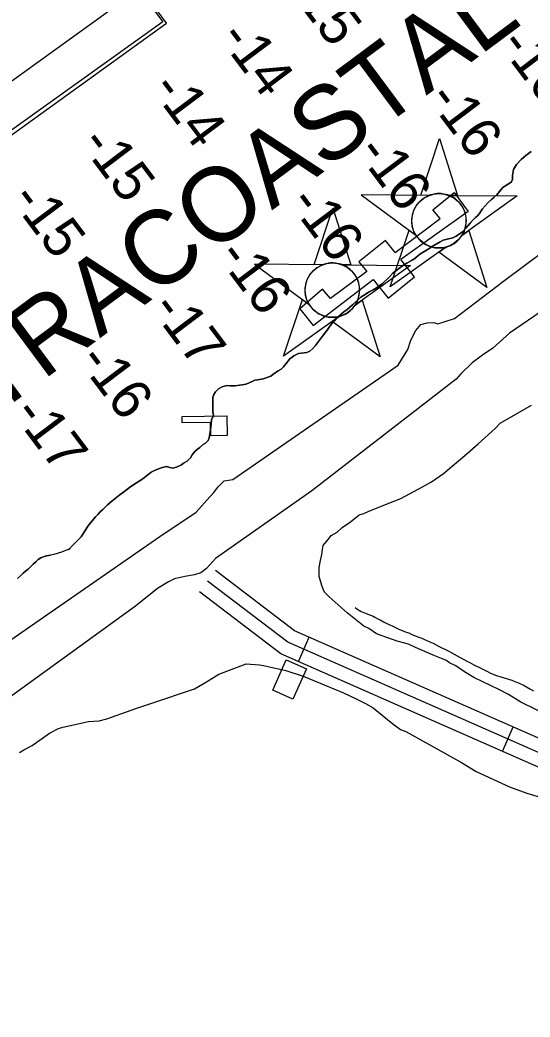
# Model space of a CAD drawing. Extents: x 3683613 to 3738215, y 469626 to 495384.
# Drawn here: x 3689919 to 3690491, y 487753 to 488872 of the extents above; entities that cross this region are included whole.
import ezdxf

# ---------------------------------------------------------------- set-up
doc = ezdxf.new("R2010")
doc.units = 0
for name, color, linetype in [('V-BLDG-OTLN', 7, 'Continuous'), ('V-CHAN-DOCK', 7, 'Continuous'), ('V-CHAN-NAID', 7, 'Continuous'), ('V-LEVE-TOET', 7, 'Continuous'), ('V-RIVR-IDEN', 7, 'Continuous'), ('V-RIVR-JETY', 7, 'Continuous'), ('V-ROAD-CNTR', 7, 'Continuous'), ('V-SITE-VEGE', 7, 'Continuous'), ('V-TOPO-SHOR', 7, 'Continuous'), ('V-TOPO-SPOT', 7, 'Continuous')]:
    doc.layers.add(name, color=color, linetype=linetype)

msp = doc.modelspace()

# ---------------------------------------------------------------- linework, layer by layer
at = {"layer": 'V-BLDG-OTLN'}
msp.add_lwpolyline([(3690217.4, 488154.1), (3690240, 488144), (3690224.8, 488109.9), (3690202.3, 488119.9)], close=True, dxfattribs=at)
at = {"layer": 'V-CHAN-DOCK'}
for points in [[(3689729.2, 488673.5), (3690051.7, 488906.3), (3690078.8, 488869.6), (3689754.7, 488637.6), (3689729.2, 488673.5)], [(3690339.7, 488610.8), (3690390.2, 488648.8), (3690382, 488658.8), (3690406, 488677.9), (3690421.6, 488656.8), (3690345.9, 488602.9)], [(3690339.7, 488610.8), (3690328.9, 488624.4), (3690298.9, 488600.5), (3690307.8, 488589.4)], [(3690314.9, 488580.4), (3690331.6, 488559.5), (3690361.5, 488583.4), (3690345.9, 488602.9)], [(3690307.8, 488589.4), (3690266.9, 488559.2), (3690258.1, 488569.5), (3690232.8, 488547.7), (3690247.8, 488528.9), (3690314.9, 488580.4)], [(3690100.5, 488426.7), (3690150.7, 488427.6), (3690151, 488405.6), (3690132.9, 488405.3), (3690132.6, 488420.1), (3690100.6, 488419.6), (3690100.5, 488426.7)]]:
    msp.add_lwpolyline(points, dxfattribs=at)
at = {"layer": 'V-CHAN-NAID'}
for points in [[(3690378, 488674.9), (3690368.4, 488675), (3690389.5, 488738.5), (3690409.7, 488674.7), (3690400.1, 488674.8), (3690398.6, 488675.3), (3690396.5, 488676), (3690394.4, 488676.4), (3690392.4, 488676.7), (3690391.2, 488676.8), (3690389.7, 488676.9), (3690388, 488676.9), (3690386.6, 488676.8), (3690384.7, 488676.6), (3690383.3, 488676.4), (3690381.5, 488676), (3690380, 488675.6), (3690379, 488675.3)], [(3690378, 488674.9), (3690301.5, 488675.5), (3690363, 488630.1), (3690361.9, 488632), (3690361.1, 488633.6), (3690360.3, 488635.6), (3690359.6, 488637.6), (3690359.2, 488638.9), (3690358.9, 488640.6), (3690358.6, 488642), (3690358.4, 488643.6), (3690358.3, 488645.4), (3690358.3, 488646.9), (3690358.4, 488649), (3690358.6, 488650.6), (3690359, 488652.8), (3690359.5, 488654.7), (3690360.1, 488656.6), (3690360.7, 488658.3), (3690361.5, 488659.9), (3690362.3, 488661.4), (3690363.3, 488663.2), (3690364.4, 488664.6), (3690365.4, 488665.9), (3690366.4, 488667.1), (3690367.7, 488668.4), (3690368.7, 488669.4), (3690370.4, 488670.8), (3690371.7, 488671.6), (3690373.3, 488672.7), (3690375.1, 488673.6), (3690376.5, 488674.3)], [(3690400.1, 488674.8), (3690476.6, 488674.2), (3690414.4, 488629.7), (3690415.3, 488631.2), (3690416.3, 488633), (3690417, 488634.6), (3690417.8, 488636.6), (3690418.3, 488638.4), (3690418.7, 488640), (3690419.1, 488642), (3690419.3, 488643.6), (3690419.4, 488645.8), (3690419.3, 488647.8), (3690419.2, 488650.1), (3690418.9, 488651.8), (3690418.4, 488654.1), (3690417.8, 488656.2), (3690417, 488658.2), (3690416.4, 488659.6), (3690415.4, 488661.5), (3690414.3, 488663.3), (3690413.1, 488665), (3690411.8, 488666.5), (3690410.5, 488667.9), (3690408.9, 488669.4), (3690407.2, 488670.8), (3690405.5, 488672), (3690403.6, 488673.1), (3690402.1, 488673.9)], [(3690258.3, 488597.1), (3690248.7, 488597.2), (3690269.8, 488660.7), (3690290, 488596.9), (3690280.4, 488597), (3690278.9, 488597.6), (3690276.8, 488598.2), (3690274.7, 488598.6), (3690272.7, 488598.9), (3690271.5, 488599), (3690270, 488599.1), (3690268.3, 488599.1), (3690266.9, 488599.1), (3690265, 488598.9), (3690263.6, 488598.6), (3690261.8, 488598.2), (3690260.3, 488597.8), (3690259.3, 488597.5)], [(3690396.4, 488616.8), (3690334.2, 488572.3), (3690355.3, 488635.8), (3690363, 488630.1), (3690363.7, 488629.1), (3690365, 488627.2), (3690366.3, 488625.8), (3690367.7, 488624.3), (3690369.1, 488623.1), (3690370.6, 488621.9), (3690372, 488620.9), (3690373.6, 488619.9), (3690375.4, 488619), (3690377.2, 488618.2), (3690378.6, 488617.6), (3690380.2, 488617.1), (3690382.5, 488616.5), (3690384, 488616.2), (3690386, 488616), (3690387.5, 488615.9), (3690389.4, 488615.9), (3690391.1, 488615.9), (3690392.8, 488616.1), (3690394.7, 488616.4)], [(3690414.4, 488629.7), (3690422.2, 488635.3), (3690442.4, 488571.5), (3690388.6, 488611.2), (3690396.4, 488616.8), (3690398.1, 488617.3), (3690399.7, 488617.8), (3690401.8, 488618.7), (3690403.6, 488619.6), (3690405.4, 488620.7), (3690407.2, 488622), (3690408.7, 488623.2), (3690410, 488624.4), (3690411.4, 488625.8), (3690412.6, 488627.2), (3690413.7, 488628.7)], [(3690258.3, 488597.1), (3690181.8, 488597.7), (3690243.3, 488552.3), (3690242.2, 488554.2), (3690241.4, 488555.8), (3690240.6, 488557.8), (3690239.9, 488559.8), (3690239.5, 488561.2), (3690239.2, 488562.8), (3690238.9, 488564.2), (3690238.7, 488565.8), (3690238.6, 488567.6), (3690238.6, 488569.1), (3690238.7, 488571.2), (3690238.9, 488572.8), (3690239.3, 488575), (3690239.8, 488577), (3690240.4, 488578.8), (3690241, 488580.5), (3690241.8, 488582.1), (3690242.6, 488583.6), (3690243.6, 488585.4), (3690244.7, 488586.9), (3690245.7, 488588.1), (3690246.7, 488589.3), (3690248, 488590.6), (3690249, 488591.6), (3690250.7, 488593), (3690251.9, 488593.8), (3690253.6, 488594.9), (3690255.4, 488595.9), (3690256.8, 488596.5)], [(3690280.4, 488597), (3690356.9, 488596.4), (3690294.7, 488551.9), (3690295.6, 488553.4), (3690296.6, 488555.2), (3690297.3, 488556.8), (3690298.1, 488558.8), (3690298.6, 488560.6), (3690299, 488562.2), (3690299.4, 488564.2), (3690299.5, 488565.8), (3690299.7, 488568), (3690299.6, 488570.1), (3690299.5, 488572.3), (3690299.2, 488574), (3690298.7, 488576.3), (3690298.1, 488578.4), (3690297.3, 488580.4), (3690296.7, 488581.8), (3690295.7, 488583.7), (3690294.6, 488585.5), (3690293.4, 488587.2), (3690292.1, 488588.7), (3690290.8, 488590.1), (3690289.2, 488591.6), (3690287.5, 488593), (3690285.8, 488594.2), (3690283.9, 488595.3), (3690282.4, 488596.1)], [(3690276.7, 488539), (3690214.5, 488494.5), (3690235.6, 488558), (3690243.3, 488552.3), (3690244, 488551.3), (3690245.3, 488549.4), (3690246.6, 488548), (3690248, 488546.5), (3690249.4, 488545.3), (3690250.9, 488544.1), (3690252.3, 488543.1), (3690253.9, 488542.1), (3690255.7, 488541.2), (3690257.5, 488540.4), (3690258.9, 488539.8), (3690260.5, 488539.3), (3690262.8, 488538.7), (3690264.3, 488538.4), (3690266.3, 488538.2), (3690267.8, 488538.1), (3690269.7, 488538.1), (3690271.4, 488538.1), (3690273.1, 488538.3), (3690275, 488538.6)], [(3690294.7, 488551.9), (3690302.5, 488557.5), (3690322.7, 488493.7), (3690268.9, 488533.4), (3690276.7, 488539), (3690278.4, 488539.5), (3690280, 488540), (3690282.1, 488541), (3690283.9, 488541.8), (3690285.7, 488542.9), (3690287.5, 488544.2), (3690289, 488545.4), (3690290.3, 488546.6), (3690291.7, 488548), (3690292.9, 488549.4), (3690294, 488550.9)]]:
    msp.add_lwpolyline(points, close=True, dxfattribs=at)
for centre in [(3690388.8, 488646.4), (3690269.1, 488568.6)]:
    msp.add_circle(centre, 30.5, dxfattribs=at)
at = {"layer": 'V-LEVE-TOET'}
for points in [[(3689105.7, 487581.6), (3689560.4, 487919.8), (3689902.5, 488172.2), (3690075.6, 488292.2), (3690116.4, 488319.5), (3690128.4, 488333.2), (3690136.2, 488341.7), (3690141.2, 488348), (3690147.6, 488354.6), (3690157.5, 488356.4), (3690157.5, 488356.4), (3690342.9, 488484.5), (3690354, 488502.2), (3690357.4, 488512.6), (3690362.8, 488523.2), (3690368.3, 488530), (3690375.5, 488532.1), (3690383.1, 488532.2), (3690387.6, 488530.7), (3690406.4, 488536.9), (3690461.3, 488578.5), (3690620.2, 488697)], [(3690509.3, 488548.8), (3690468.1, 488520.3), (3690449.1, 488503.5), (3690437.7, 488495.6), (3690426.1, 488487.2), (3690413.5, 488474.9), (3690408, 488468.7), (3690246.3, 488343.7), (3690138.2, 488267.5), (3690128.1, 488256.5), (3690121.6, 488251.4), (3690114.4, 488249.4), (3690103.6, 488247.3), (3690092.2, 488244.7), (3690085.4, 488241.5), (3690072.9, 488234), (3690048.2, 488214), (3689864.6, 488081.4), (3689587.4, 487879.9), (3689268.9, 487643.8)]]:
    msp.add_lwpolyline(points, dxfattribs=at)
at = {"layer": 'V-RIVR-JETY'}
for points in [[(3690471.3, 488694.8), (3690471.3, 488697), (3690472.5, 488703.7), (3690475.7, 488709.5), (3690481.2, 488715), (3690486.4, 488719.5), (3690492.3, 488723.9)], [(3689996.1, 488305.6), (3689999.5, 488309.9), (3690003.5, 488314.4), (3690006, 488317.1), (3690008.6, 488319.9), (3690011.7, 488322.7), (3690017, 488327.8), (3690021.8, 488332), (3690030.9, 488339.3), (3690036.4, 488343.3), (3690041.7, 488347.4), (3690047.6, 488351.4), (3690054.4, 488355.5), (3690058.4, 488358.5), (3690065.7, 488364.4), (3690070.2, 488366.6), (3690075.3, 488368.5), (3690078.2, 488369.6), (3690078.6, 488369.7)], [(3689915.9, 488245.1), (3689919.3, 488248.3), (3689922.2, 488251.3), (3689924.8, 488253.4), (3689927.9, 488255.8), (3689933.6, 488261.1), (3689936.4, 488263.9), (3689939.1, 488266.4), (3689942.1, 488268.3), (3689946.7, 488270.3), (3689952.4, 488271.3)]]:
    msp.add_lwpolyline(points, dxfattribs=at)
at = {"layer": 'V-ROAD-CNTR'}
for p, q in [((3690231.2, 488152), (3690243.3, 488179.5)), ((3690460.1, 488051.3), (3690472.2, 488078.8))]:
    msp.add_line(p, q, dxfattribs=at)
for points in [[(3691864.8, 487432.3), (3690851, 487912.2), (3690226.8, 488186.7), (3690138.1, 488254.2)], [(3691871.9, 487412.4), (3690844.8, 487898.5), (3690219.2, 488173.7), (3690129, 488242.3)], [(3691840.8, 487410.5), (3690838.5, 487884.9), (3690211.5, 488160.7), (3690119.9, 488230.3)]]:
    msp.add_lwpolyline(points, dxfattribs=at)
at = {"layer": 'V-SITE-VEGE'}
for points in [[(3690515.8, 488089.4), (3690480.6, 488106.5), (3690466.9, 488115.1), (3690456.1, 488120.7), (3690428.1, 488134.3), (3690417.3, 488140.7), (3690407.9, 488147.1), (3690400.7, 488150.6), (3690396.4, 488153.5), (3690393.5, 488154.9), (3690384.2, 488158.5), (3690362.6, 488167.7), (3690355.4, 488171.2), (3690350.4, 488172.7), (3690341.7, 488174.8), (3690318.7, 488183.3), (3690310.1, 488189), (3690304.3, 488191.8), (3690285.6, 488206.8), (3690265.4, 488224.7), (3690260.4, 488229.7), (3690258.9, 488233.2), (3690257.5, 488237.5), (3690254.5, 488247.6), (3690254.5, 488257.6), (3690255.9, 488265.5), (3690257.3, 488272), (3690258, 488277.7), (3690258.7, 488282.1), (3690265.8, 488290.7), (3690268, 488293.6), (3690274.4, 488297.2), (3690280.1, 488302.3), (3690289.4, 488308.8), (3690299.4, 488316.7), (3690304.5, 488318.2), (3690309.5, 488320.3), (3690332.4, 488329.8), (3690346, 488334.9), (3690370.4, 488347.9), (3690380.4, 488353.7), (3690394, 488363.1), (3690420.4, 488385.5), (3690432.6, 488396.3), (3690451.9, 488413.6), (3690457.6, 488419.4), (3690492.7, 488439.6)], [(3689918.1, 488050.1), (3689923.1, 488053), (3689932.4, 488058), (3689951.7, 488071.7), (3689961.7, 488076.8), (3689966.8, 488078.3), (3689995.4, 488084.9), (3690007.6, 488085.6), (3690016.2, 488087.8), (3690048.5, 488099.5), (3690066.4, 488105.3), (3690114.4, 488121.3), (3690128, 488129.3), (3690141.6, 488138), (3690172.4, 488149.6), (3690187.5, 488148.2), (3690191.8, 488147.5), (3690217, 488141.9), (3690236.4, 488135.5), (3690249.3, 488130.6), (3690281.7, 488117.1), (3690296.8, 488110), (3690306.2, 488105), (3690314.8, 488100), (3690337.1, 488082.2)], [(3690337.1, 488082.2), (3690345.8, 488075.7), (3690351.5, 488073.6), (3690414.1, 488038.7), (3690430.7, 488028.8), (3690468.1, 488011.7), (3690487.5, 488004.6), (3690506.2, 487999)]]:
    msp.add_lwpolyline(points, dxfattribs=at)
at = {"layer": 'V-TOPO-SHOR'}
for points in [[(3689755.1, 488631.6), (3690082.9, 488867.8), (3690044.3, 488921.2)], [(3690492.3, 488723.9), (3690486.4, 488719.5), (3690481.2, 488715), (3690475.7, 488709.5), (3690472.5, 488703.7), (3690471.3, 488697), (3690471.3, 488694.8), (3690471.3, 488692.9), (3690470, 488690.2), (3690467.7, 488688), (3690464.4, 488686.3), (3690461, 488684), (3690458.4, 488681), (3690453.8, 488675.3), (3690450.2, 488672.5), (3690447.7, 488670.2), (3690443.9, 488667), (3690437.2, 488659.3), (3690434.4, 488654.4), (3690431.9, 488652.1), (3690429.6, 488649.7), (3690426.8, 488647), (3690423.9, 488643.6), (3690418.8, 488638.2), (3690415.2, 488634), (3690408.1, 488629.3), (3690404.5, 488627.4), (3690396.6, 488625.4), (3690393.5, 488624.8), (3690390.1, 488622.9), (3690382.9, 488618.6), (3690376.6, 488614.5), (3690371.1, 488611.1), (3690367.5, 488608.8), (3690361.8, 488604.1), (3690358, 488602), (3690352.9, 488598.8), (3690348.9, 488596.6), (3690346.4, 488594.9), (3690337.1, 488587.5), (3690332.9, 488583.2), (3690324.9, 488575.8), (3690318.7, 488571.3), (3690314.9, 488568.9), (3690310.3, 488566.8), (3690304.2, 488562.7), (3690301.2, 488560.6), (3690296.6, 488556.6), (3690291.9, 488552.1), (3690288.6, 488549.5), (3690285.6, 488547), (3690282, 488544.2), (3690276.1, 488538.9), (3690272.5, 488535.1), (3690270, 488533.1), (3690266.2, 488528.3), (3690263.5, 488523.8), (3690258, 488517), (3690255.7, 488513.8), (3690250.2, 488506.6), (3690247.3, 488503), (3690243.9, 488500.2), (3690240.7, 488498.7), (3690231.2, 488497.6), (3690225.9, 488495), (3690221.5, 488491.4), (3690217.5, 488486.3), (3690214.3, 488482.5), (3690211.6, 488479.9), (3690208.2, 488478), (3690205, 488475.7)], [(3690471.3, 488694.8), (3690471.3, 488697), (3690472.5, 488703.7), (3690475.7, 488709.5), (3690481.2, 488715), (3690486.4, 488719.5), (3690492.3, 488723.9)], [(3690450.2, 488672.5), (3690453.8, 488675.3), (3690458.4, 488681), (3690461, 488684), (3690464.4, 488686.3), (3690467.7, 488688), (3690470, 488690.2), (3690471.3, 488692.9), (3690471.3, 488694.8)], [(3690078.6, 488369.7), (3690082.9, 488370.7), (3690086.9, 488369.6), (3690090.3, 488369), (3690094.1, 488369.9), (3690099.8, 488372.7), (3690102.3, 488374.4), (3690106.4, 488376.9), (3690109.9, 488380.5), (3690112, 488383.9), (3690115, 488387.5), (3690117.9, 488390.1), (3690120.3, 488392.2), (3690124.3, 488395.4), (3690126.8, 488397.1), (3690129.8, 488399.9), (3690131, 488402.9), (3690131.8, 488407.3), (3690132.5, 488411.4), (3690132.9, 488415.2), (3690133.1, 488418.6), (3690133.7, 488423), (3690135.6, 488427.9), (3690135.1, 488432.1), (3690134.9, 488435.9), (3690134.9, 488440.6), (3690135.1, 488445), (3690135, 488448.2), (3690136.1, 488451.4), (3690138, 488454.6), (3690141.4, 488458), (3690145.4, 488460.3), (3690150.7, 488461.6), (3690154.9, 488461.2), (3690160, 488461.3), (3690164.8, 488461.9), (3690168, 488462.3), (3690172, 488463), (3690175, 488464.3), (3690182, 488467.7), (3690185.4, 488468.1), (3690191.7, 488469.2), (3690200, 488472), (3690202.3, 488473.9), (3690205, 488475.7), (3690208.2, 488478), (3690211.6, 488479.9), (3690214.3, 488482.5), (3690217.5, 488486.3), (3690221.5, 488491.4), (3690225.9, 488495), (3690231.2, 488497.6), (3690240.7, 488498.7), (3690243.9, 488500.2), (3690247.3, 488503), (3690250.2, 488506.6), (3690255.7, 488513.8), (3690258, 488517), (3690263.5, 488523.8), (3690266.2, 488528.3), (3690270, 488533.1), (3690272.5, 488535.1), (3690276.1, 488538.9), (3690282, 488544.2), (3690285.6, 488547), (3690288.6, 488549.5), (3690291.9, 488552.1), (3690296.6, 488556.6), (3690301.2, 488560.6), (3690304.2, 488562.7), (3690310.3, 488566.8), (3690314.9, 488568.9), (3690318.7, 488571.3), (3690324.9, 488575.8), (3690332.9, 488583.2), (3690337.1, 488587.5), (3690346.4, 488594.9), (3690348.9, 488596.6), (3690352.9, 488598.8), (3690358, 488602), (3690361.8, 488604.1), (3690367.5, 488608.8), (3690371.1, 488611.1), (3690376.6, 488614.5), (3690382.9, 488618.6), (3690390.1, 488622.9), (3690393.5, 488624.8), (3690396.6, 488625.4), (3690404.5, 488627.4), (3690408.1, 488629.3), (3690415.2, 488634), (3690418.8, 488638.2), (3690423.9, 488643.6), (3690426.8, 488647), (3690429.6, 488649.7), (3690431.9, 488652.1), (3690434.4, 488654.4), (3690437.2, 488659.3), (3690443.9, 488667), (3690447.7, 488670.2), (3690450.2, 488672.5)], [(3690205, 488475.7), (3690202.3, 488473.9), (3690200, 488472), (3690191.7, 488469.2), (3690185.4, 488468.1), (3690182, 488467.7), (3690175, 488464.3), (3690172, 488463), (3690168, 488462.3), (3690164.8, 488461.9), (3690160, 488461.3), (3690154.9, 488461.2), (3690150.7, 488461.6), (3690145.4, 488460.3), (3690141.4, 488458), (3690138, 488454.6), (3690136.1, 488451.4), (3690135, 488448.2), (3690135.1, 488445), (3690134.9, 488440.6), (3690134.9, 488435.9), (3690135.1, 488432.1), (3690135.6, 488427.9), (3690133.7, 488423), (3690133.1, 488418.6), (3690132.9, 488415.2), (3690132.5, 488411.4), (3690131.8, 488407.3), (3690131, 488402.9), (3690129.8, 488399.9), (3690126.8, 488397.1), (3690124.3, 488395.4), (3690120.3, 488392.2), (3690117.9, 488390.1), (3690115, 488387.5), (3690112, 488383.9), (3690109.9, 488380.5), (3690106.4, 488376.9), (3690102.3, 488374.4), (3690099.8, 488372.7), (3690094.1, 488369.9), (3690090.3, 488369), (3690086.9, 488369.6), (3690082.9, 488370.7), (3690078.6, 488369.7), (3690078.2, 488369.6), (3690075.3, 488368.5), (3690070.2, 488366.6), (3690065.7, 488364.4), (3690058.4, 488358.5), (3690054.4, 488355.5), (3690047.6, 488351.4), (3690041.7, 488347.4), (3690036.4, 488343.3), (3690030.9, 488339.3), (3690021.8, 488332), (3690017, 488327.8), (3690011.7, 488322.7), (3690008.6, 488319.9), (3690006, 488317.1), (3690003.5, 488314.4), (3689999.5, 488309.9), (3689996.1, 488305.6), (3689995.1, 488304.4), (3689991.1, 488297.8), (3689987.3, 488291.9), (3689984.3, 488288.9), (3689977.6, 488282.1), (3689974.2, 488278.4), (3689972.9, 488277.9), (3689969.8, 488276.5), (3689965.1, 488274.8), (3689956.5, 488272), (3689952.7, 488271.4), (3689952.4, 488271.3), (3689946.7, 488270.3), (3689942.1, 488268.3), (3689939.1, 488266.4), (3689936.4, 488263.9), (3689933.6, 488261.1), (3689927.9, 488255.8), (3689924.8, 488253.4), (3689922.2, 488251.3), (3689919.3, 488248.3), (3689915.9, 488245.1)], [(3689972.9, 488277.9), (3689974.2, 488278.4), (3689977.6, 488282.1), (3689984.3, 488288.9), (3689987.3, 488291.9), (3689991.1, 488297.8), (3689995.1, 488304.4), (3689996.1, 488305.6)], [(3689915.9, 488245.1), (3689919.3, 488248.3), (3689922.2, 488251.3), (3689924.8, 488253.4), (3689927.9, 488255.8), (3689933.6, 488261.1), (3689936.4, 488263.9), (3689939.1, 488266.4), (3689942.1, 488268.3), (3689946.7, 488270.3), (3689952.4, 488271.3)], [(3690294.9, 488212.7), (3690296.8, 488211.2), (3690301.5, 488208.3), (3690305.1, 488206.8), (3690311.9, 488204.1), (3690315.1, 488202.8), (3690317, 488202), (3690319.6, 488200.5), (3690322.7, 488198.8), (3690324.6, 488197.6), (3690326.6, 488196.5), (3690329.7, 488195), (3690333.8, 488193.2), (3690337, 488191.7), (3690338.7, 488190.9), (3690343.8, 488188.3), (3690352, 488185.2), (3690354.8, 488184.2), (3690358.4, 488182.5), (3690365.2, 488179.8), (3690366.2, 488179.3), (3690368.6, 488178.7), (3690378.6, 488174.3), (3690380.3, 488173.5), (3690382.2, 488172.6), (3690388.3, 488169.3), (3690399.1, 488164.2), (3690403.2, 488161.9), (3690409.3, 488158.6), (3690420.8, 488152.1), (3690422.7, 488151.2), (3690427.8, 488148.5), (3690436.5, 488144.1), (3690438, 488143.4), (3690441.6, 488141.6), (3690443.9, 488140.5), (3690446.7, 488139), (3690453.3, 488136.3), (3690458.4, 488134.9), (3690470.5, 488131.1), (3690474.1, 488129.8), (3690477.9, 488128.2), (3690484.3, 488125.2), (3690490.6, 488121.5), (3690494.9, 488119.1)]]:
    msp.add_lwpolyline(points, dxfattribs=at)

# ---------------------------------------------------------------- texts
at = {"layer": 'V-RIVR-IDEN'}
msp.add_text('INTRACOASTAL WATERWAY (ALTERNATE ROUTE)', height=83, rotation=36.615, dxfattribs=at).set_placement((3689800.3, 488359.9))
at = {"layer": 'V-TOPO-SPOT'}
for s, p in [('-15', (3690217, 488908.2)), ('-14', (3690140.8, 488851.5)), ('-16', (3690455.1, 488843.6)), ('-14', (3690064.7, 488794.1)), ('-16', (3690374.9, 488783)), ('-15', (3689985, 488733.1)), ('-16', (3690295.2, 488723.4)), ('-15', (3689907, 488670.3)), ('-16', (3690219.3, 488666.5)), ('-16', (3690138.7, 488606.8)), ('-17', (3690064.3, 488547.7)), ('-16', (3689982.8, 488489.5)), ('-17', (3689909.3, 488429.9))]:
    msp.add_text(s, height=45, rotation=306.9347, dxfattribs=at).set_placement(p)

doc.saveas('drawing.dxf')
